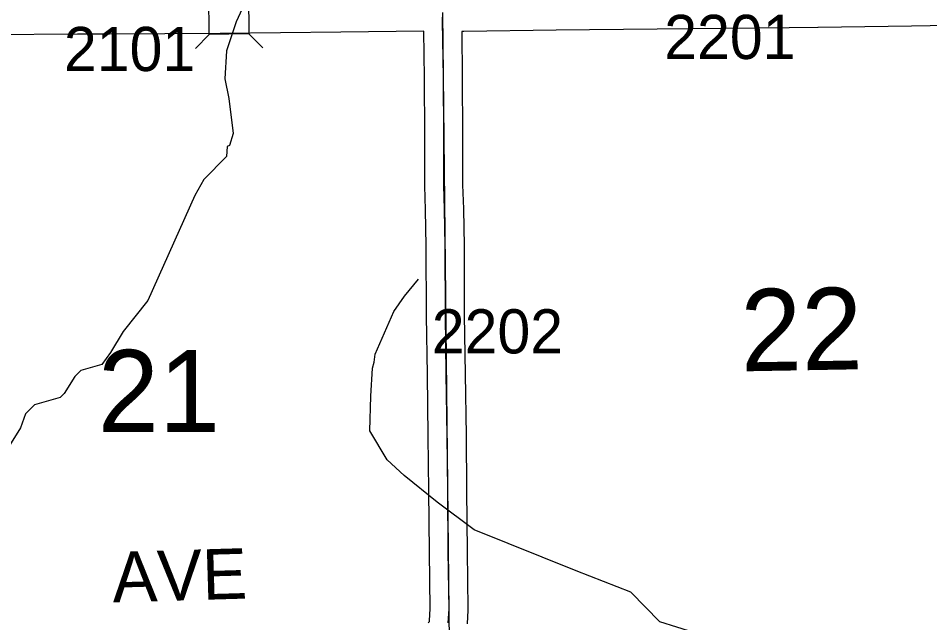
# Model space of a CAD drawing. Extents: x 23.6 to 68.7, y -63 to -29.
# Drawn here: x 35.142 to 36.588, y -55.691 to -54.733 of the extents above; entities that cross this region are included whole.
import ezdxf

# ---------------------------------------------------------------- set-up
doc = ezdxf.new("R2010")
doc.units = 0
for name, color, linetype in [('tdCoHydroRiver', 7, 'Continuous'), ('tdCoSecRdNmbr', 7, 'Continuous'), ('tdCoSecRdTxt', 7, 'Continuous'), ('tdCoSecRteBand', 7, 'Continuous'), ('tdCoSecRteCL', 7, 'Continuous'), ('tdCoSectLine', 7, 'Continuous'), ('tdCoSectNmbr', 7, 'Continuous'), ('tdCoStrucSec', 7, 'Continuous'), ('tdCoSurfGravel', 7, 'Continuous')]:
    doc.layers.add(name, color=color, linetype=linetype)

msp = doc.modelspace()

# ---------------------------------------------------------------- linework, layer by layer
at = {"layer": 'tdCoHydroRiver'}
for points in [[(35.4974, -54.7179), (35.4881, -54.7385), (35.4727, -54.7844), (35.4699, -54.8287), (35.4765, -54.8602), (35.4832, -54.9154), (35.4771, -54.9344), (35.4739, -54.936), (35.4725, -54.9518), (35.4365, -54.9884), (35.4225, -55.0137), (35.348, -55.1801), (35.3089, -55.2293), (35.2887, -55.2627), (35.2746, -55.2817), (35.2416, -55.2915), (35.2322, -55.301), (35.215, -55.328), (35.2088, -55.3343), (35.1678, -55.3457), (35.1537, -55.36), (35.146, -55.3822), (35.1008, -55.4536)], [(36.2141, -55.7067), (36.1603, -55.6898), (36.1142, -55.6428), (36.0271, -55.6087), (35.8655, -55.5437), (35.8068, -55.5), (35.7544, -55.4578), (35.7273, -55.4328), (35.7001, -55.3872), (35.7013, -55.332), (35.7041, -55.2877), (35.7071, -55.2782), (35.7086, -55.2656), (35.7381, -55.1975), (35.7552, -55.1737), (35.7771, -55.1466)]]:
    msp.add_lwpolyline(points, dxfattribs=at)
at = {"layer": 'tdCoSecRteBand'}
for points in [[(36.7375, -54.7421), (36.5592, -54.7453), (36.5592, -54.7453), (36.5592, -54.7453), (36.4112, -54.7476), (36.411, -54.7476), (36.4109, -54.7476), (36.365, -54.7478), (36.2101, -54.7498), (36.21, -54.7498), (36.21, -54.7498), (36.0482, -54.7512), (35.9956, -54.7518), (35.8489, -54.7537), (35.8486, -54.7537), (35.8482, -54.7537), (35.8457, -54.7537), (35.8466, -54.8266), (35.8466, -54.8267), (35.8466, -54.8268), (35.8472, -54.9178), (35.8472, -54.9179), (35.8472, -54.918), (35.8472, -54.9972), (35.8484, -55.035), (35.8484, -55.0352), (35.8484, -55.0354), (35.8494, -55.0934), (35.8494, -55.0936), (35.8494, -55.0938), (35.8498, -55.2037), (35.8512, -55.2969), (35.8512, -55.2969), (35.8512, -55.2969), (35.8526, -55.3946), (35.8526, -55.3946), (35.8526, -55.3946), (35.8535, -55.4813), (35.8535, -55.4813), (35.8535, -55.4813), (35.8545, -55.5781), (35.8557, -55.6694), (35.8557, -55.6704), (35.8557, -55.6715), (35.8545, -55.693)], [(35.7927, -55.6915), (35.7932, -55.6909), (35.7937, -55.6903), (35.7941, -55.6896), (35.7944, -55.689), (35.7946, -55.6882), (35.7947, -55.6877), (35.7957, -55.6692), (35.7945, -55.5789), (35.7945, -55.5788), (35.7945, -55.5788), (35.7935, -55.4819), (35.7926, -55.3954), (35.7912, -55.2978), (35.7898, -55.2045), (35.7898, -55.2043), (35.7898, -55.2041), (35.7894, -55.0942), (35.7884, -55.0366), (35.7872, -54.9986), (35.7872, -54.9981), (35.7872, -54.9977), (35.7872, -54.9181), (35.7866, -54.8273), (35.7857, -54.7535), (35.6541, -54.7549), (35.6541, -54.7549), (35.6541, -54.7549), (35.4625, -54.7569), (35.4625, -54.7569), (35.4624, -54.7569), (35.2868, -54.7583), (35.2866, -54.7583), (35.2864, -54.7583), (35.2363, -54.7579), (35.0979, -54.7591)]]:
    msp.add_lwpolyline(points, dxfattribs=at)
at = {"layer": 'tdCoSecRteCL'}
msp.add_lwpolyline([(35.8245, -55.6913), (35.8257, -55.6698), (35.8245, -55.5785), (35.8235, -55.4816), (35.8226, -55.395), (35.8212, -55.2973), (35.8198, -55.204), (35.8194, -55.0939), (35.8184, -55.0359), (35.8172, -54.9977), (35.8172, -54.918), (35.8166, -54.827), (35.8155, -54.738), (35.8156, -54.7235)], dxfattribs=at)
at = {"layer": 'tdCoSectLine'}
msp.add_lwpolyline([(35.8152, -54.7235), (35.8256, -55.7233)], dxfattribs=at)
at = {"layer": 'tdCoStrucSec'}
for p, q in [((35.4453, -54.7584), (35.4234, -54.7807)), ((35.5079, -54.7577), (35.5303, -54.7796))]:
    msp.add_line(p, q, dxfattribs=at)
msp.add_lwpolyline([(35.4447, -54.6958), (35.5073, -54.6951), (35.5079, -54.7577), (35.4453, -54.7584)], close=True, dxfattribs=at)
at = {"layer": 'tdCoSurfGravel'}
msp.add_lwpolyline([(35.8245, -55.6913), (35.8257, -55.6698), (35.8245, -55.5785), (35.8235, -55.4816), (35.8226, -55.395), (35.8212, -55.2973), (35.8198, -55.204), (35.8194, -55.0939), (35.8184, -55.0359), (35.8172, -54.9977), (35.8172, -54.918), (35.8166, -54.827), (35.8155, -54.738), (35.8156, -54.7235)], dxfattribs=at)

# ---------------------------------------------------------------- texts
at = {"layer": 'tdCoSecRdNmbr'}
for s, rotation, p in [('2201', 0.0285, (36.167, -54.7975)), ('2101', 0.0277, (35.2147, -54.8166)), ('2202', 0.0282, (35.7983, -55.2643))]:
    msp.add_text(s, height=0.07, rotation=rotation, dxfattribs=at).set_placement(p)
at = {"layer": 'tdCoSecRdTxt'}
msp.add_text('AVE', height=0.08, rotation=1.6891, dxfattribs=at).set_placement((35.2924, -55.6591))
at = {"layer": 'tdCoSectNmbr'}
for s, rotation, p in [('22', 1.0285, (36.2892, -55.2927)), ('21', 0.0278, (35.2687, -55.3887))]:
    msp.add_text(s, height=0.13, rotation=rotation, dxfattribs=at).set_placement(p)

doc.saveas('drawing.dxf')
